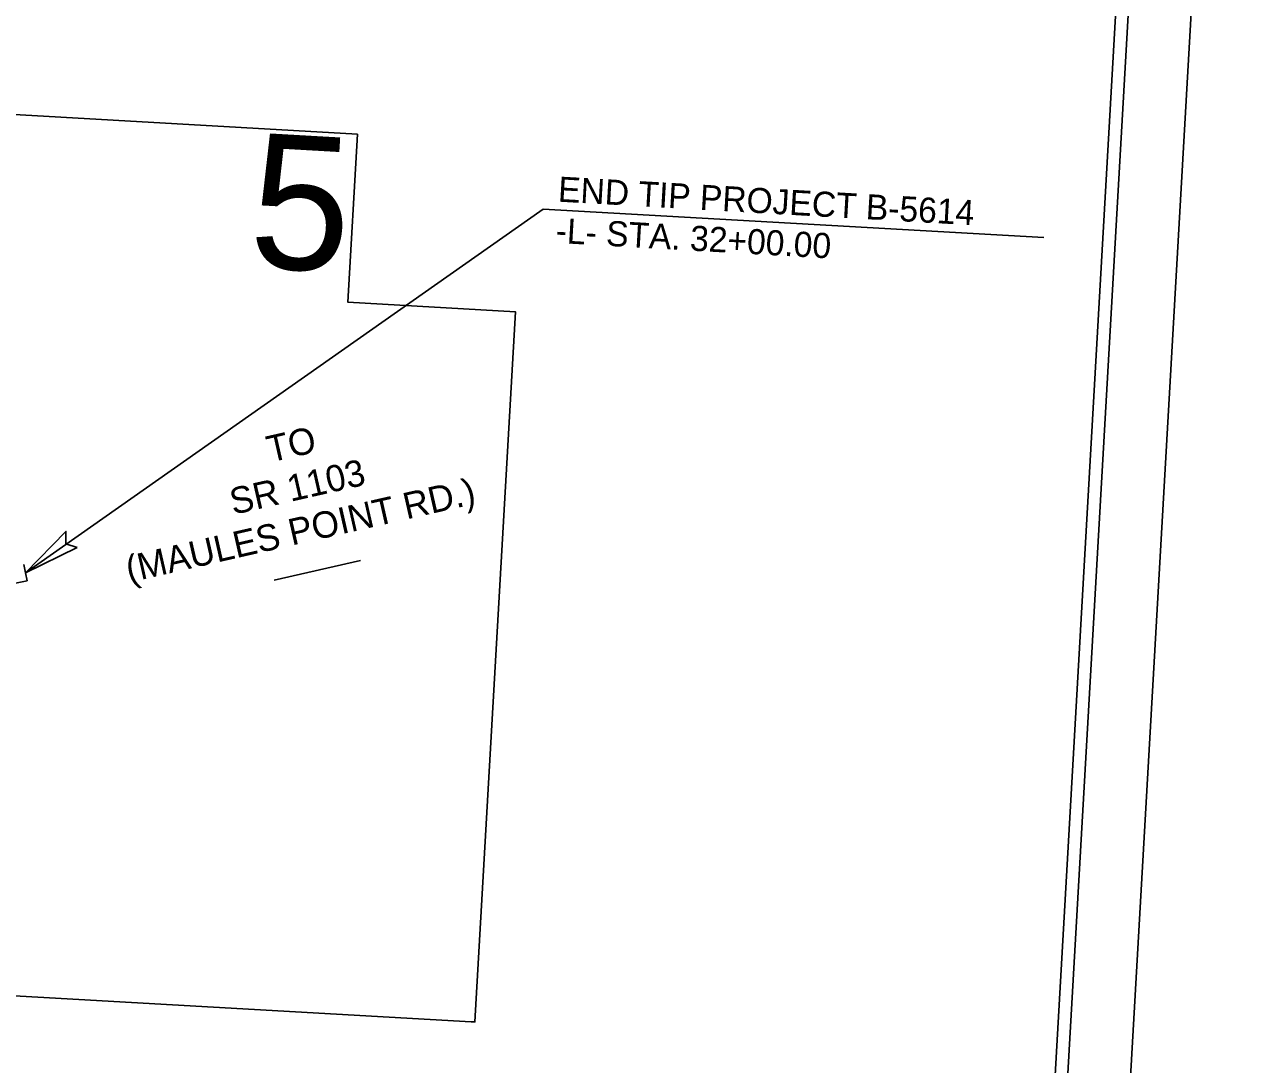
# Model space of a CAD drawing. Extents: x 2601627 to 2606907, y 616646 to 620530.
# Drawn here: x 2605452 to 2606907, y 617888 to 619130 of the extents above; entities that cross this region are included whole.
import ezdxf

# ---------------------------------------------------------------- set-up
doc = ezdxf.new("R2010")
doc.units = 0
for name, color, linetype in [('Exist Roads EOP Leader', 7, 'Continuous'), ('Exist Roads EOP Text', 7, 'Continuous'), ('Prop Horizontal Alignment Station Label', 7, 'Continuous'), ('Prop Shade Light', 7, 'Continuous'), ('Prop Terminator CELL', 7, 'Continuous'), ('Sheet Data Field CELL', 7, 'Continuous'), ('Sheet Title CELL', 7, 'Continuous'), ('Stewart Plot Border Xerox6279 and LJ5000', 7, 'Continuous')]:
    doc.layers.add(name, color=color, linetype=linetype)

msp = doc.modelspace()

# ---------------------------------------------------------------- linework, layer by layer
at = {"layer": 'Exist Roads EOP Leader'}
msp.add_line((2605853, 618489.5), (2605749.8, 618466.2), dxfattribs=at)
at = {"layer": 'Prop Horizontal Alignment Station Label'}
msp.add_lwpolyline([(2605453.3, 618475.1), (2606070.9, 618909.1), (2606668.1, 618875.1)], dxfattribs=at)
at = {"layer": 'Prop Shade Light'}
msp.add_line((2605414.2, 618457.2), (2605455.3, 618465.3), dxfattribs=at)
msp.add_lwpolyline([(2605455.3, 618465.3), (2605453.3, 618475.1), (2605451.4, 618485)], dxfattribs=at)
at = {"layer": 'Prop Terminator CELL'}
msp.add_lwpolyline([(2605515, 618505), (2605453.3, 618475.1), (2605501.5, 618524.4), (2605501.5, 618509.7)], close=True, dxfattribs=at)
at = {"layer": 'Sheet Title CELL'}
for p, q in [((2604589.3, 619070.3), (2605849.4, 618998.6)), ((2605984.9, 617939.2), (2604529.6, 618022))]:
    msp.add_line(p, q, dxfattribs=at)
for points in [[(2606650, 617053.9), (2606825.7, 620138.9)], [(2606667.4, 617623.8), (2606809.9, 620124.8)], [(2605849.4, 618998.6), (2605837.9, 618797.8), (2605837.9, 618797.8)], [(2605837.9, 618797.8), (2606037.7, 618786.5), (2605989.4, 617938.9), (2605984.9, 617939.2)]]:
    msp.add_lwpolyline(points, dxfattribs=at)
at = {"layer": 'Stewart Plot Border Xerox6279 and LJ5000'}
msp.add_lwpolyline([(2601627.1, 617234.9), (2606718.9, 616944.8), (2606906.6, 620239.5), (2601814.8, 620529.5)], close=True, dxfattribs=at)

# ---------------------------------------------------------------- texts
at = {"layer": 'Exist Roads EOP Text'}
for s, p in [('TO', (2605745.1, 618606.6)), ('SR 1103', (2605701, 618544.1)), ('(MAULES POINT RD.)', (2605576.9, 618463.3))]:
    msp.add_text(s, height=31.5, rotation=12.8218, dxfattribs=at).set_placement(p)
at = {"layer": 'Prop Horizontal Alignment Station Label'}
for s, p in [('END TIP PROJECT B-5614', (2606088, 618918)), ('-L- STA. 32+00.00', (2606085.2, 618868.8))]:
    msp.add_text(s, height=30, rotation=356.7398, dxfattribs=at).set_placement(p)
at = {"layer": 'Sheet Data Field CELL'}
msp.add_text('5', height=160.4, rotation=356.7398, dxfattribs=at).set_placement((2605718, 618840.2))

doc.saveas('drawing.dxf')
